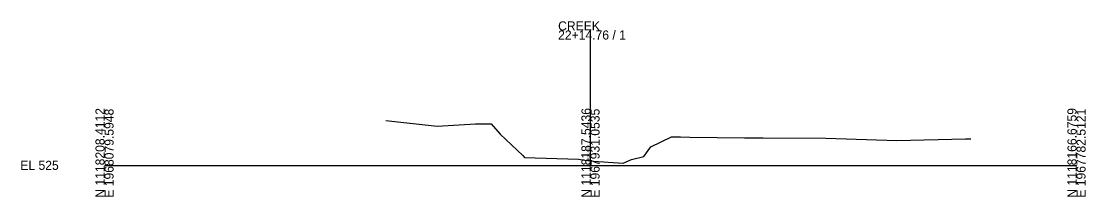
# Model space of a CAD drawing. Extents: x 9974 to 10303, y 9990 to 19550.
# Drawn here: x 9974.3 to 10302.8, y 11990.3 to 12044.5 of the extents above; entities that cross this region are included whole.
import ezdxf

# ---------------------------------------------------------------- set-up
doc = ezdxf.new("R2010")
doc.units = 0
for name, color, linetype in [('Level 10', 7, 'Continuous'), ('Level 60', 7, 'Continuous'), ('Level 63', 7, 'Continuous')]:
    doc.layers.add(name, color=color, linetype=linetype)

msp = doc.modelspace()

# ---------------------------------------------------------------- linework, layer by layer
at = {"layer": 'Level 60'}
for p, q in [((10086.85, 12013.88), (10102.66, 12012.14)), ((10102.66, 12012.14), (10114.47, 12012.78)), ((10114.47, 12012.78), (10115.86, 12012.79)), ((10115.86, 12012.79), (10119.33, 12012.82)), ((10119.33, 12012.82), (10122.1, 12009.6)), ((10122.1, 12009.6), (10129.07, 12002.99)), ((10168.63, 12005.72), (10174.96, 12008.82)), ((10174.96, 12008.82), (10177.74, 12008.79)), ((10177.74, 12008.79), (10180.7, 12008.74)), ((10180.7, 12008.74), (10197.55, 12008.52)), ((10197.55, 12008.52), (10203.25, 12008.45)), ((10203.25, 12008.45), (10222.61, 12008.42)), ((10222.61, 12008.42), (10244.55, 12007.62)), ((10244.55, 12007.62), (10265.74, 12008.17)), ((10265.74, 12008.17), (10266.84, 12008.19)), ((10266.84, 12008.19), (10267.39, 12008.19)), ((10166.46, 12002.74), (10168.63, 12005.72)), ((10129.07, 12002.99), (10129.59, 12002.4)), ((10129.59, 12002.4), (10146.29, 12001.92)), ((10146.29, 12001.92), (10148.24, 12001.56)), ((10148.24, 12001.56), (10150, 12001.35)), ((10150, 12001.35), (10150.97, 12001.24)), ((10160.03, 12000.66), (10162.61, 12001.76)), ((10162.61, 12001.76), (10166.46, 12002.74)), ((10150.97, 12001.24), (10160.03, 12000.66))]:
    msp.add_line(p, q, dxfattribs=at)
at = {"layer": 'Level 63'}
for p, q in [((10150, 12000), (10150, 12041.65)), ((10000, 12000), (10150, 12000)), ((10150, 12000), (10300, 12000))]:
    msp.add_line(p, q, dxfattribs=at)

# ---------------------------------------------------------------- texts
at = {"layer": 'Level 10'}
msp.add_text('526.353', height=0.8, rotation=90, dxfattribs=at).set_placement((10149.9, 12001.85))
at = {"layer": 'Level 63'}
for s, p in [('CREEK', (10140, 12041.65)), ('22+14.76 / 1', (10140, 12038.85)), ('EL 525', (9974, 11998.6))]:
    msp.add_text(s, height=2.8, dxfattribs=at).set_placement(p)
for s, p in [('N 1118208.4112', (10000, 11990)), ('E 1968079.5948', (10002.8, 11990)), ('N 1118187.5436', (10150, 11990)), ('E 1967931.0535', (10152.8, 11990)), ('N 1118166.6759', (10300, 11990)), ('E 1967782.5121', (10302.8, 11990))]:
    msp.add_text(s, height=2.8, rotation=90, dxfattribs=at).set_placement(p)

doc.saveas('drawing.dxf')
